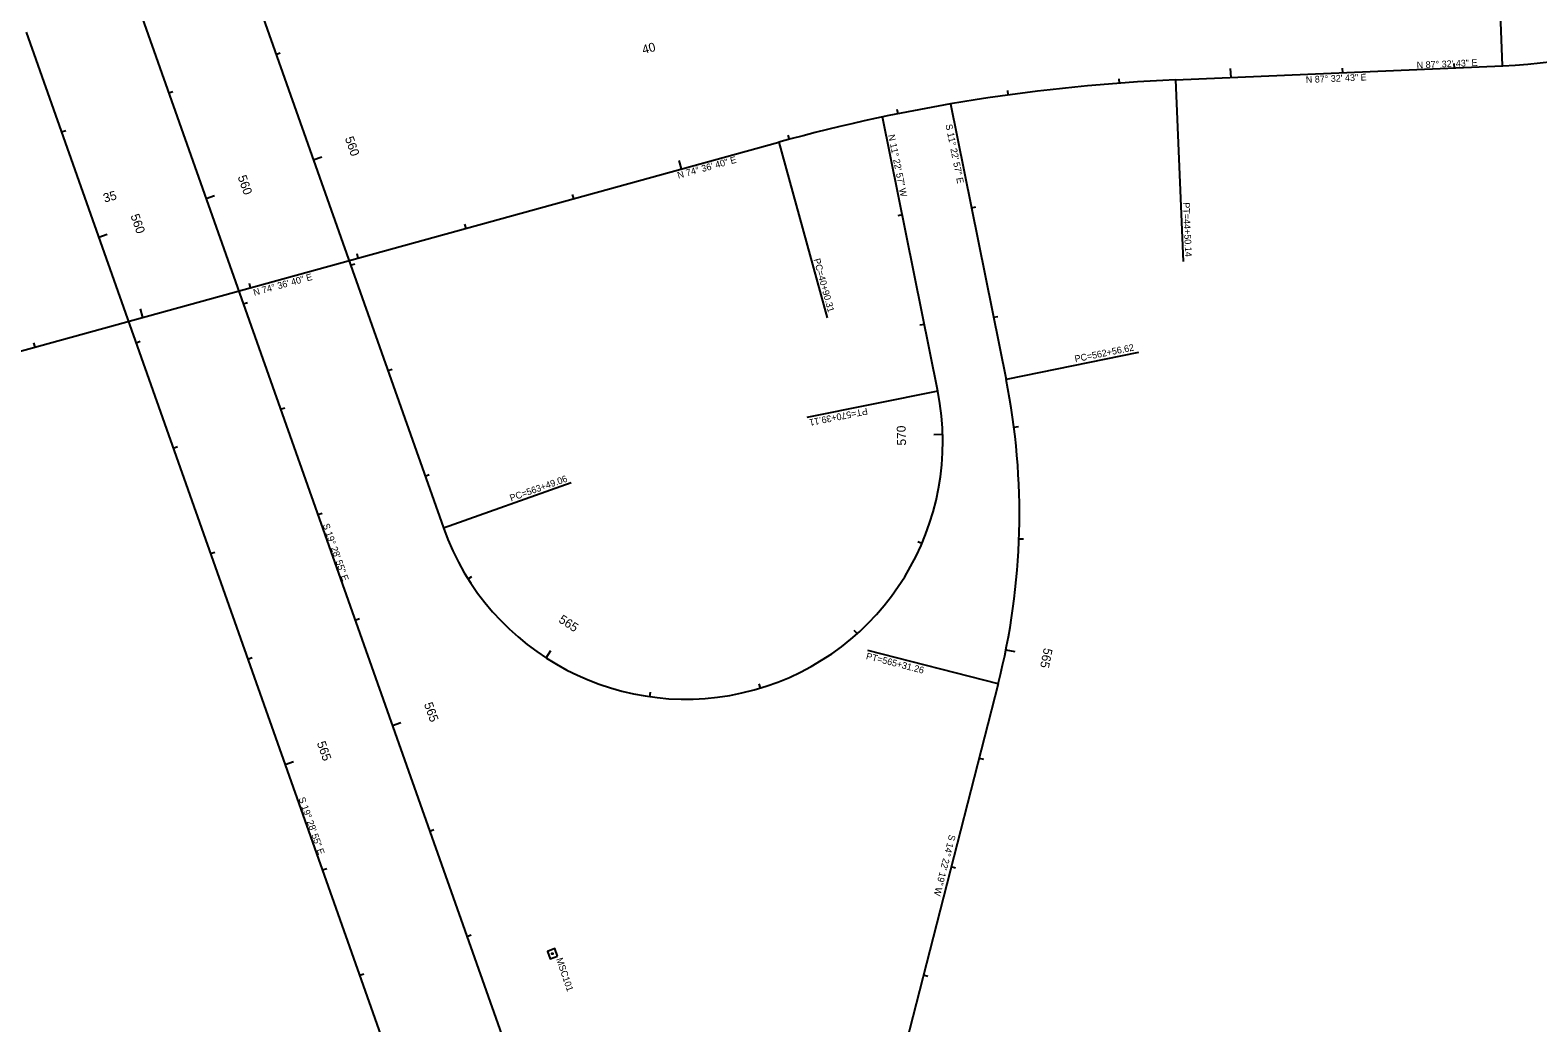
# Model space of a CAD drawing. Extents: x 2004390 to 2008791, y 1133870 to 1140084.
# Drawn here: x 2005751 to 2007099, y 1136432 to 1137320 of the extents above; entities that cross this region are included whole.
import ezdxf

# ---------------------------------------------------------------- set-up
doc = ezdxf.new("R2010")
doc.units = 0
for name, color, linetype in [('RD_HC_Cl', 7, 'Continuous'), ('RD_HC_CL_Rel', 7, 'Continuous'), ('RD_HC_Data', 7, 'Continuous'), ('RD_HC_Data_Rel', 7, 'Continuous'), ('RD_HC_Data_Tic', 7, 'Continuous'), ('RD_HC_Data_Tic_Rel', 7, 'Continuous'), ('RD_HC_Survey', 7, 'Continuous'), ('RD_HC_Survey_txCode', 7, 'Continuous'), ('RD_HC_TX_Rel_Sta50', 7, 'Continuous'), ('RD_HC_TX_Sta50', 7, 'Continuous')]:
    doc.layers.add(name, color=color, linetype=linetype)

msp = doc.modelspace()

# ---------------------------------------------------------------- linework, layer by layer
at = {"layer": 'RD_HC_Cl'}
for p, q in [((2005036.1, 1139633.5), (2007075.2, 1133869.8)), ((2005746.4, 1137931.6), (2006120.3, 1136874.9)), ((2005747, 1137318.2), (2006250.3, 1135895.5)), ((2006562.6, 1136997), (2006513.2, 1137242.2)), ((2006574.1, 1137253.9), (2006623.7, 1137007.6)), ((2006616.6, 1136735.3), (2006480.1, 1136202.9))]:
    msp.add_line(p, q, dxfattribs=at)
for centre, radius, start in [((2006024.7, 1136887), 611, 345.6281), ((2006337.1, 1136951.6), 230, 199.482)]:
    msp.add_arc(centre, radius, start, 11.3824, dxfattribs=at)
at = {"layer": 'RD_HC_CL_Rel'}
for p, q in [((2006775.2, 1137275.3), (2007068, 1137287.9)), ((2005534.9, 1136975.9), (2006420.4, 1137219.7))]:
    msp.add_line(p, q, dxfattribs=at)
for centre, radius, start, end in [((2007047.3, 1137772.5), 485, 272.4547, 353.919), ((2006843.4, 1135682.8), 1594, 92.4547, 105.3889)]:
    msp.add_arc(centre, radius, start, end, dxfattribs=at)
at = {"layer": 'RD_HC_Data'}
for p, q in [((2006742.3, 1137031.5), (2006623.7, 1137007.6)), ((2006562.6, 1136997), (2006445.4, 1136973.4)), ((2006120.3, 1136874.9), (2006234.7, 1136915.3)), ((2006616.6, 1136735.3), (2006500, 1136765.2))]:
    msp.add_line(p, q, dxfattribs=at)
at = {"layer": 'RD_HC_Data_Rel'}
for p, q in [((2007068, 1137287.9), (2007061, 1137452)), ((2006775.2, 1137275.3), (2006782.1, 1137113)), ((2006420.4, 1137219.7), (2006463.6, 1137062.7))]:
    msp.add_line(p, q, dxfattribs=at)
at = {"layer": 'RD_HC_Data_Tic'}
for p, q in [((2005970.5, 1137298.2), (2005974.3, 1137299.5)), ((2005874.5, 1137263.7), (2005878.3, 1137265)), ((2005778.6, 1137228.9), (2005782.4, 1137230.2)), ((2006003.8, 1137203.9), (2006011.4, 1137206.6)), ((2005907.9, 1137169.4), (2005915.4, 1137172)), ((2006592.8, 1137161.1), (2006596.7, 1137161.9)), ((2006530.8, 1137154.7), (2006526.9, 1137153.9)), ((2005812, 1137134.6), (2005819.5, 1137137.3)), ((2006037.2, 1137109.7), (2006041, 1137111)), ((2005941.2, 1137075.1), (2005945, 1137076.4)), ((2006550.6, 1137056.7), (2006546.6, 1137055.9)), ((2006612.5, 1137063.1), (2006616.4, 1137063.9)), ((2005845.3, 1137040.3), (2005849.1, 1137041.7)), ((2006070.5, 1137015.4), (2006074.3, 1137016.7)), ((2005974.6, 1136980.8), (2005978.3, 1136982.2)), ((2006630.7, 1136964.8), (2006634.7, 1136965.3)), ((2005878.7, 1136946.1), (2005882.5, 1136947.4)), ((2006567, 1136958.2), (2006559, 1136957.9)), ((2006103.9, 1136921.1), (2006107.7, 1136922.4)), ((2006007.9, 1136886.6), (2006011.7, 1136887.9)), ((2006635.3, 1136865), (2006639.3, 1136864.9)), ((2005912, 1136851.8), (2005915.8, 1136853.1)), ((2006548.4, 1136860.7), (2006544.7, 1136862.3)), ((2006142.4, 1136829.1), (2006145.8, 1136831.2)), ((2006041.3, 1136792.3), (2006045.1, 1136793.6)), ((2006490.4, 1136780.2), (2006487.8, 1136783.1)), ((2005945.4, 1136757.5), (2005949.2, 1136758.9)), ((2006212.1, 1136758.5), (2006216.5, 1136765.2)), ((2006623.6, 1136765.8), (2006631.4, 1136764.2)), ((2006404, 1136731.5), (2006402.8, 1136735.3)), ((2006305.1, 1136723.8), (2006305.6, 1136727.8)), ((2006074.6, 1136698), (2006082.2, 1136700.7)), ((2005978.7, 1136663.2), (2005986.3, 1136665.9)), ((2006599.5, 1136668.7), (2006603.4, 1136667.8)), ((2006108, 1136603.7), (2006111.8, 1136605.1)), ((2006012.1, 1136569), (2006015.9, 1136570.3)), ((2006574.7, 1136571.9), (2006578.6, 1136570.9)), ((2006141.3, 1136509.5), (2006145.1, 1136510.8)), ((2006045.4, 1136474.7), (2006049.2, 1136476)), ((2006549.9, 1136475), (2006553.7, 1136474))]:
    msp.add_line(p, q, dxfattribs=at)
at = {"layer": 'RD_HC_Data_Tic_Rel'}
for p, q in [((2006825, 1137277.5), (2006824.6, 1137285.5)), ((2006924.9, 1137281.8), (2006924.7, 1137285.8)), ((2007024.8, 1137286), (2007024.6, 1137290)), ((2006725.1, 1137272.4), (2006724.8, 1137276.4)), ((2006625.7, 1137261.9), (2006625.2, 1137265.8)), ((2006527.1, 1137245.1), (2006526.3, 1137249)), ((2006429.8, 1137222.2), (2006428.8, 1137226.1)), ((2006333.4, 1137195.7), (2006331.3, 1137203.4)), ((2006237, 1137169.2), (2006235.9, 1137173)), ((2006140.6, 1137142.6), (2006139.5, 1137146.5)), ((2006044.1, 1137116.1), (2006043.1, 1137119.9)), ((2005947.7, 1137089.5), (2005946.7, 1137093.4)), ((2005851.3, 1137063), (2005849.2, 1137070.7)), ((2005754.9, 1137036.5), (2005753.8, 1137040.3))]:
    msp.add_line(p, q, dxfattribs=at)
at = {"layer": 'RD_HC_Survey'}
msp.add_lwpolyline([(2006222.3, 1136491.8), (2006220, 1136498.5), (2006213.3, 1136496.1), (2006215.7, 1136489.5)], close=True, dxfattribs=at)
msp.add_circle((2006217.8, 1136494), 0.5, dxfattribs=at)

# ---------------------------------------------------------------- texts
at = {"layer": 'RD_HC_Data'}
for s, rotation, p in [('S 11%%d 22\' 57" E', 281.3824, (2006569.5, 1137235.2)), ('N 11%%d 22\' 57" W', 281.3824, (2006518.2, 1137226)), ('PC=562+56.62', 11.3824, (2006685.7, 1137022.8)), ('PT=570+39.11', 191.3824, (2006499.2, 1136982.2)), ('PC=563+49.06', 19.482, (2006180.9, 1136898.4)), ('S 19%%d 28\' 55" E', 289.482, (2006012.2, 1136877.5)), ('PT=565+31.26', 345.6281, (2006498, 1136757.5)), ('S 19%%d 28\' 55" E', 289.482, (2005990.6, 1136632.8)), ('S 14%%d 22\' 19" W', 255.6281, (2006572.9, 1136601))]:
    msp.add_text(s, height=6, rotation=rotation, dxfattribs=at).set_placement(p)
at = {"layer": 'RD_HC_Data_Rel'}
for s, rotation, p in [('N 87%%d 32\' 43" E', 2.4547, (2006991.2, 1137285.6)), ('N 87%%d 32\' 43" E', 2.4547, (2006892, 1137272.6)), ('N 74%%d 36\' 40" E', 15.3889, (2006330.5, 1137187)), ('PT=44+50.14', 272.4547, (2006781.9, 1137165.7)), ('PC=40+90.31', 285.3889, (2006451.4, 1137114.8)), ('N 74%%d 36\' 40" E', 15.3889, (2005951.1, 1137082.2))]:
    msp.add_text(s, height=6, rotation=rotation, dxfattribs=at).set_placement(p)
at = {"layer": 'RD_HC_Survey_txCode'}
msp.add_text('MSC101', height=6, rotation=288.8025, dxfattribs=at).set_placement((2006221.1, 1136489.2))
at = {"layer": 'RD_HC_TX_Rel_Sta50'}
for s, p in [('40', (2006299.3, 1137298.3)), ('35', (2005817.2, 1137165.6))]:
    msp.add_text(s, height=8, rotation=15.3889, dxfattribs=at).set_placement(p)
at = {"layer": 'RD_HC_TX_Sta50'}
for s, rotation, p in [('560', 289.482, (2006032, 1137223.2)), ('560', 289.482, (2005936.1, 1137188.6)), ('560', 289.482, (2005840.2, 1137153.9)), ('570', 91.6396, (2006534.3, 1136948.5)), ('565', 327.0836, (2006222.7, 1136790.9)), ('565', 258.5593, (2006657.6, 1136767.8)), ('565', 289.482, (2006102.8, 1136717.2)), ('565', 289.482, (2006006.9, 1136682.4))]:
    msp.add_text(s, height=8, rotation=rotation, dxfattribs=at).set_placement(p)

doc.saveas('drawing.dxf')
